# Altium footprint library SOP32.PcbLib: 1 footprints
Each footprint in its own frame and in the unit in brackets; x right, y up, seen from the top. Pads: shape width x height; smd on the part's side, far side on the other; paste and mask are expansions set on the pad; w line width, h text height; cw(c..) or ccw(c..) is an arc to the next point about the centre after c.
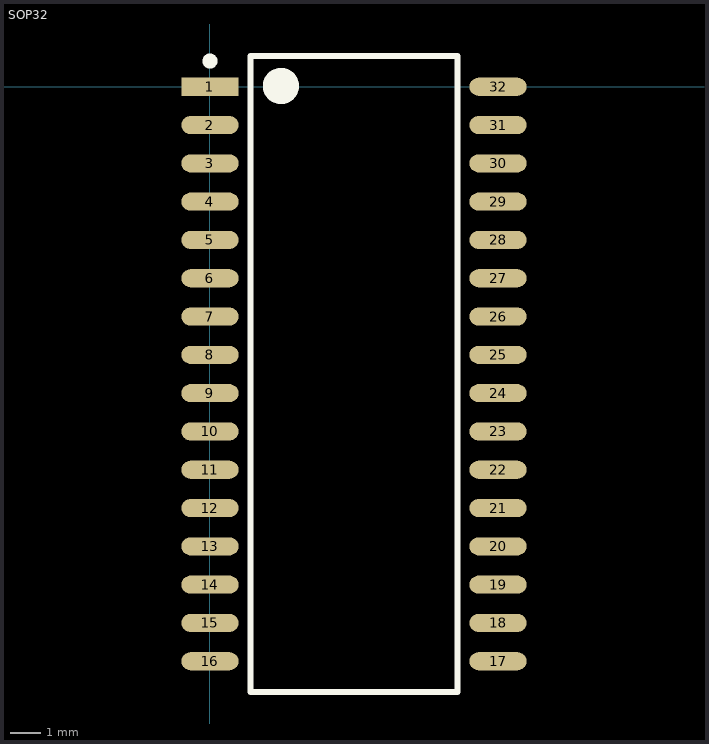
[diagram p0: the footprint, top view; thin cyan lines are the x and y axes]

## SOP32 [mm] "SOP, 32-Leads, Body 21.1x7.6mm (max), Pitch 1.27mm, IPC Medium Density"
height 2.34
pads (32):
  rect 1.9x0.6 smd: 1(0,0)
  oval 1.9x0.6 smd: 2(0,-1.27) 3(0,-2.54) 4(0,-3.81) 5(0,-5.08) 6(0,-6.35) 7(0,-7.62) 8(0,-8.89) 9(0,-10.16) 10(0,-11.43) 11(0,-12.7) 12(0,-13.97) 13(0,-15.24) 14(0,-16.51) 15(0,-17.78) 16(0,-19.05) 17(9.55,-19.05) 18(9.55,-17.78) 19(9.55,-16.51) 20(9.55,-15.24) 21(9.55,-13.97) 22(9.55,-12.7) 23(9.55,-11.43) 24(9.55,-10.16) 25(9.55,-8.89) 26(9.55,-7.62) 27(9.55,-6.35) 28(9.55,-5.08) 29(9.55,-3.81) 30(9.55,-2.54) 31(9.55,-1.27) 32(9.55,0)
Top Overlay:
  circle w0.6: c2.35,0.025 r0.3
  circle w0.25: c0,0.85 r0.125
  lines w0.2: 1.35,-20.075 8.2,-20.075 8.2,1.025 1.35,1.025 1.35,-20.075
